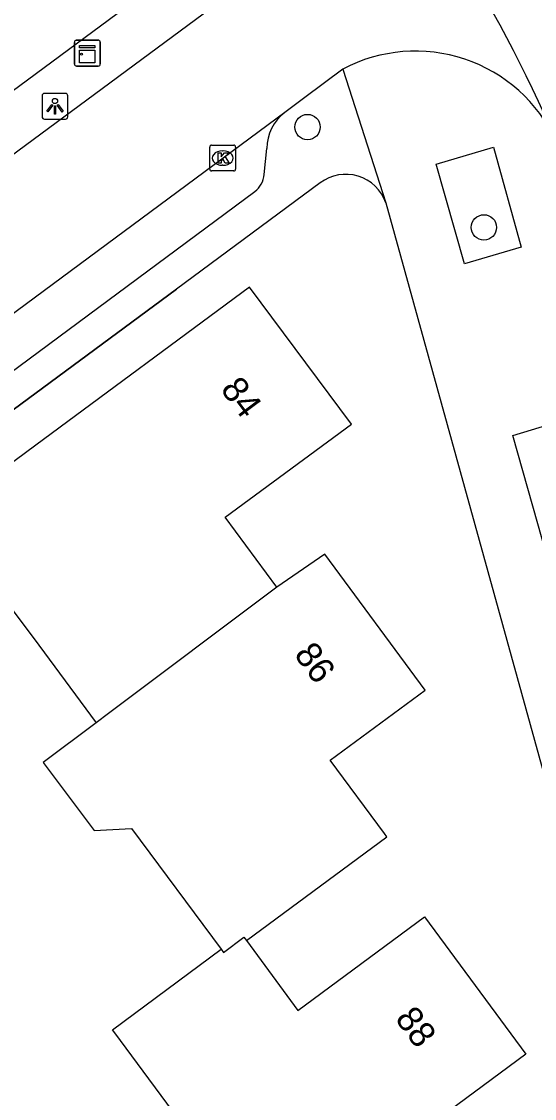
# Model space of a CAD drawing. Extents: x 163427 to 164190, y 380331 to 381641.
# Drawn here: x 163891.17 to 163911, y 381323.49 to 381365.11 of the extents above; entities that cross this region are included whole.
import ezdxf

# ---------------------------------------------------------------- set-up
doc = ezdxf.new("R2010")
doc.units = 0
for name, color, linetype in [('IMGEO_Boom', 7, 'Continuous'), ('IMGEO_Kast', 7, 'Continuous'), ('IMGEO_Kolk', 7, 'Continuous'), ('IMGEO_Lichtpunt', 7, 'Continuous'), ('IMGEO_Muur', 7, 'Continuous'), ('IMGEO_Pand', 7, 'Continuous'), ('IMGEO_Pand_nummerreeks', 7, 'Continuous'), ('IMGEO_Rijbaan_lokaal_gesloten', 7, 'Continuous'), ('IMGEO_Rijbaan_lokaal_open', 7, 'Continuous'), ('IMGEO_Voetpad_open', 7, 'Continuous')]:
    doc.layers.add(name, color=color, linetype=linetype)

msp = doc.modelspace()

# ---------------------------------------------------------------- linework, layer by layer
at = {"layer": 'IMGEO_Boom'}
for centre in [(163902.226, 381361.034), (163909.044, 381357.156)]:
    msp.add_circle(centre, 0.489, dxfattribs=at)
at = {"layer": 'IMGEO_Kast'}
for p, q in [((163893.288, 381364.392), (163894.129, 381364.392)), ((163894.129, 381364.392), (163893.288, 381364.392)), ((163893.213, 381363.467), (163893.213, 381364.308)), ((163893.213, 381364.308), (163893.213, 381363.467)), ((163894.213, 381364.317), (163894.213, 381363.476)), ((163894.213, 381363.476), (163894.213, 381364.317)), ((163894.138, 381363.392), (163893.297, 381363.392)), ((163893.297, 381363.392), (163894.138, 381363.392))]:
    msp.add_line(p, q, dxfattribs=at)
for points in [[(163893.408, 381364.182), (163894.008, 381364.182), (163894.008, 381364.097), (163893.408, 381364.097), (163893.408, 381364.182)], [(163893.408, 381364.007), (163894.008, 381364.007), (163894.008, 381363.518), (163893.408, 381363.518), (163893.408, 381364.007)]]:
    msp.add_lwpolyline(points, dxfattribs=at)
msp.add_circle((163893.492, 381363.856), 0.0377, dxfattribs=at)
for centre, start, end in [((163893.291, 381364.314), 92.4484, 184.2845), ((163893.291, 381364.314), 92.4484, 184.2845), ((163894.135, 381364.314), 2.4484, 94.2845), ((163894.135, 381364.314), 2.4484, 94.2845), ((163893.291, 381363.47), 182.4484, 274.2845), ((163893.291, 381363.47), 182.4484, 274.2845), ((163894.135, 381363.47), 272.4484, 4.2845), ((163894.135, 381363.47), 272.4484, 4.2845)]:
    msp.add_arc(centre, 0.0779, start, end, dxfattribs=at)
at = {"layer": 'IMGEO_Kolk'}
for p, q in [((163898.446, 381359.41), (163898.446, 381360.262)), ((163898.521, 381360.336), (163899.373, 381360.336)), ((163899.447, 381360.262), (163899.447, 381359.41)), ((163898.934, 381360.116), (163898.959, 381360.116)), ((163899.373, 381359.336), (163898.521, 381359.336)), ((163898.957, 381359.556), (163898.932, 381359.556))]:
    msp.add_line(p, q, dxfattribs=at)
for points in [[(163898.446, 381359.41), (163898.446, 381360.262)], [(163898.521, 381360.336), (163899.373, 381360.336)], [(163899.447, 381360.262), (163899.447, 381359.41)], [(163898.767, 381360.036), (163898.89, 381360.036), (163898.89, 381359.885), (163899.02, 381360.036), (163899.184, 381360.036), (163899.038, 381359.885), (163899.191, 381359.636), (163899.039, 381359.636), (163898.954, 381359.8), (163898.89, 381359.733), (163898.89, 381359.636), (163898.767, 381359.636), (163898.767, 381360.036)], [(163899.373, 381359.336), (163898.521, 381359.336)]]:
    msp.add_lwpolyline(points, dxfattribs=at)
for centre, start, end in [((163898.523, 381360.26), 91.552, 178.448), ((163898.523, 381360.26), 91.552, 178.448), ((163899.371, 381360.26), 1.552, 88.448), ((163899.371, 381360.26), 1.552, 88.448), ((163898.523, 381359.412), 181.552, 268.448), ((163898.523, 381359.412), 181.552, 268.448), ((163899.371, 381359.412), 271.552, 358.448), ((163899.371, 381359.412), 271.552, 358.448)]:
    msp.add_arc(centre, 0.0765, start, end, dxfattribs=at)
for centre, major_axis, ratio, start_param, end_param in [((163898.933, 381359.836), (-0.387, 0.002), 0.722429, 4.712389, 7.853982), ((163898.958, 381359.836), (-0.39, 0.002), 0.717154, 1.570796, 4.712389)]:
    msp.add_ellipse(centre, major_axis=major_axis, ratio=ratio, start_param=start_param, end_param=end_param, dxfattribs=at)
at = {"layer": 'IMGEO_Lichtpunt'}
for p, q in [((163892.868, 381362.337), (163892.06, 381362.337)), ((163892.868, 381362.337), (163892.06, 381362.337)), ((163891.966, 381362.242), (163891.966, 381361.435)), ((163891.966, 381362.242), (163891.966, 381361.435)), ((163892.962, 381361.435), (163892.962, 381362.242)), ((163892.962, 381361.435), (163892.962, 381362.242)), ((163892.06, 381361.341), (163892.868, 381361.341)), ((163892.06, 381361.341), (163892.868, 381361.341))]:
    msp.add_line(p, q, dxfattribs=at)
for points in [[(163892.34, 381361.906), (163892.379, 381361.878), (163892.191, 381361.616), (163892.153, 381361.643), (163892.34, 381361.906)], [(163892.442, 381361.858), (163892.489, 381361.858), (163892.489, 381361.536), (163892.442, 381361.536), (163892.442, 381361.858)], [(163892.552, 381361.878), (163892.59, 381361.905), (163892.777, 381361.643), (163892.738, 381361.615), (163892.552, 381361.878)]]:
    msp.add_lwpolyline(points, dxfattribs=at)
msp.add_circle((163892.465, 381362.04), 0.0994, dxfattribs=at)
for centre, start, end in [((163892.06, 381362.242), 90, 180), ((163892.06, 381362.242), 90, 180), ((163892.868, 381362.242), 0, 90), ((163892.868, 381362.242), 0, 90), ((163892.06, 381361.435), 180, 270), ((163892.06, 381361.435), 180, 270), ((163892.868, 381361.435), 270, 0), ((163892.868, 381361.435), 270, 360)]:
    msp.add_arc(centre, 0.0946, start, end, dxfattribs=at)
at = {"layer": 'IMGEO_Muur'}
msp.add_lwpolyline([(163878.804, 381341.211), (163897.16, 381354.771)], dxfattribs=at)
at = {"layer": 'IMGEO_Pand'}
for points in [[(163901.044, 381343.248), (163899.048, 381345.955), (163903.93, 381349.553), (163899.979, 381354.841), (163891.72, 381348.736), (163888.069, 381346.037), (163891.835, 381341.003), (163894.052, 381338.007)], [(163899.862, 381329.594), (163905.291, 381333.603), (163905.196, 381333.731), (163903.102, 381336.567), (163906.767, 381339.274), (163902.889, 381344.523), (163901.044, 381343.248)], [(163901.044, 381343.248), (163894.539, 381338.372), (163894.052, 381338.007)], [(163894.052, 381338.007), (163892.009, 381336.476), (163893.979, 381333.848), (163895.428, 381333.929), (163898.886, 381329.254)], [(163899.862, 381329.594), (163901.854, 381326.895), (163906.744, 381330.506), (163910.667, 381325.204), (163907.69, 381323.004)], [(163898.886, 381329.254), (163898.976, 381329.132), (163899.77, 381329.719), (163899.862, 381329.594)], [(163902.216, 381319.325), (163899.94, 381322.402), (163898.334, 381321.213), (163897.658, 381322.126), (163894.775, 381326.025), (163894.685, 381326.146), (163898.886, 381329.254)]]:
    msp.add_lwpolyline(points, dxfattribs=at)
at = {"layer": 'IMGEO_Rijbaan_lokaal_gesloten'}
msp.add_arc((163861.382, 381338.888), 54.881, 23.2004, 41.5796, dxfattribs=at)
at = {"layer": 'IMGEO_Rijbaan_lokaal_open'}
for points in [[(163853.339, 381332.241), (163853.766, 381332.578), (163899.382, 381366.301), (163901.215, 381367.486)], [(163903.594, 381363.274), (163902.126, 381362.181), (163901.344, 381361.597)], [(163901.344, 381361.597), (163857.513, 381329.143)]]:
    msp.add_lwpolyline(points, dxfattribs=at)
msp.add_arc((163906.395, 381357.979), 5.99, 24.9731, 117.8774, dxfattribs=at)
at = {"layer": 'IMGEO_Voetpad_open'}
for points in [[(163897.686, 381367.504), (163854.312, 381335.419), (163850.881, 381332.872)], [(163903.594, 381363.274), (163905.25, 381358.102)], [(163900.551, 381359.203), (163900.651, 381360.209)], [(163908.287, 381355.747), (163907.196, 381359.606), (163909.416, 381360.258), (163910.489, 381356.395), (163908.287, 381355.747)], [(163860.751, 381329.314), (163900.189, 381358.538)], [(163902.716, 381358.876), (163897.16, 381354.771), (163878.804, 381341.211), (163867.222, 381332.654)], [(163905.25, 381358.102), (163926.328, 381281.925)], [(163912.068, 381342.379), (163910.162, 381349.117), (163912.328, 381349.775), (163914.224, 381342.952), (163912.068, 381342.379)]]:
    msp.add_lwpolyline(points, dxfattribs=at)
for centre, radius, start, end in [((163902.399, 381360.203), 1.748, 127.1195, 179.8164), ((163899.603, 381359.288), 0.952, 307.9992, 354.8765), ((163903.703, 381357.572), 1.635, 18.9047, 127.1252)]:
    msp.add_arc(centre, radius, start, end, dxfattribs=at)

# ---------------------------------------------------------------- texts
at = {"layer": 'IMGEO_Pand_nummerreeks'}
for s, rotation, p in [('84', 306.7665, (163898.833, 381350.896)), ('86', 306.4571, (163901.678, 381340.642)), ('88', 306.4981, (163905.579, 381326.566))]:
    msp.add_text(s, height=1, rotation=rotation, dxfattribs=at).set_placement(p)

doc.saveas('drawing.dxf')
